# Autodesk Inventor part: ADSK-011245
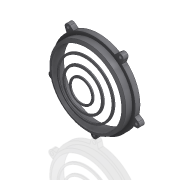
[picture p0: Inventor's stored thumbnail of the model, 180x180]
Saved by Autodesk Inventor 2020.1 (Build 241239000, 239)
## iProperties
Created: 2000-10
Part Number: ADSK-011245
Document SubType Name: Modeling
Designer: Administrator
Material: Générique
Density: 1 g/cm^3
Appearance: Metal-Steel(Polish)
Mass: 112.419 g
Surface Area: 475.801 cm^2
Volume: 112.419 cm^3
Control State: 0
Master: False
Checked Out: False
Shininess: 60.0
Length Units: 11269
Angle Units: 11279
Time Units: 11290
Mass Units: 11283
Length Display Precision: 3
Angle Display Precision: 2
Compacted: True
Dimensions: 181,7x36,9x186,1 mm
Mass: 0,112 kg
VLT_Material: Generic
Density: 0.0
Volumn: 0.0
Area: 0.0
PropertySet Name: Model Information
Author: Administrator
Revision Number: -
Title: ADSK-011245
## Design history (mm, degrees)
feature "RevolutionSrf1" dims angle "d0" = 90 deg
feature "RevolutionSrf2" dims angle "d1" = 90 deg
feature "RevolutionSrf3" dims angle "d2" = 90 deg
sketch "Sketch6"
  geometry: C1 r 84.15 at (0, 0); C2 r 78.15 at (0, 0)
  constraints: 2 centre point, 1 coincident
  dimensions: "d3" = 6 radial gap between concentric circles of C2 C1; "d6" = 168.3004 diameter of C1
extrude "Extrusion1" new body sketch "Sketch6" distance "d4" = 10; taper "d5" = 0 deg
sketch "Sketch8" dims "d9" = 182
  geometry: L1 (-6.279, -92.682)-(-8.685, -83.701); L2 (6.279, -92.682)-(8.685, -83.701); L3 (0, 0)-(0, -91); C1 r 3.25 at (0, -91); A1 r 84.15 centre (0, 0) between (-8.685, -83.701) and (8.685, -83.701) reference; A2 r 6.5 centre (0, -91) between (-6.279, -92.682) and (6.279, -92.682)
  constraints: 6 end point, 4 point on circle, 2 centre point, 2 coincident, 2 tangent, 1 vertical, 1 vertical alignment, 3 other
  dimensions: "d10" = 6.5 diameter of C1; "d11" = 13 diameter of A2; "d44" = 30 deg angle of L2 L1
extrude "Extrusion3" join sketch "Sketch8" distance "d12" = 10; taper "d13" = 0 deg
pattern_circular "Circular Pattern1" dims angle "d16" = 360 deg
sketch "Sketch12"
  geometry: C1 r 78.15 at (0, 0) reference; C2 r 72.15 at (0, 0)
  constraints: 1 centre point
  dimensions: "d33" = 6 radial gap between concentric circles of C2 C1
extrude "Extrusion6" join sketch "Sketch12" stored distance "d34" = 10; taper "d35" = 0 deg
sketch "Sketch14"
  geometry: C1 r 72.15 at (0, 0) reference; C2 r 58.374 at (0, 0); C3 r 55.002 at (0, 0); C4 r 41.949 at (0, 0); C5 r 38.109 at (0, 0); C6 r 24.766 at (0, 0); C7 r 21.384 at (0, 0)
  constraints: 6 centre point
extrude "Extrusion8" join sketch "Sketch14" stored distance "d42" = 10; taper "d43" = 0 deg
node "Solide1"
node "Corps solides"
node "Corps surfaciques"
node "Sketch1"
node "Sketch5"
sketch "Sketch2"
  geometry: L1 (0, 42.175)-(0, 21.163); A1 r 185.056 centre (4.167, -142.833) between (0, 42.175) and (-97.859, 11.557)
  constraints: 2 end point, 2 point on circle, 1 centre point
body "Srf1"
sketch "Sketch3"
  geometry: L1 (0, 38.673)-(0, 22.983); A1 r 181.554 centre (4.167, -142.833) between (0, 38.673) and (-95.928, 8.636)
  constraints: 2 end point, 2 point on circle, 1 centre point
body "Srf2"
sketch "Sketch4"
  geometry: L1 (0, 36.558)-(0, 22.706); A1 r 179.439 centre (4.167, -142.833) between (0, 36.558) and (-94.762, 6.871)
  constraints: 2 end point, 2 point on circle, 1 centre point
body "Srf3"
other parameters: "d19" = 0
